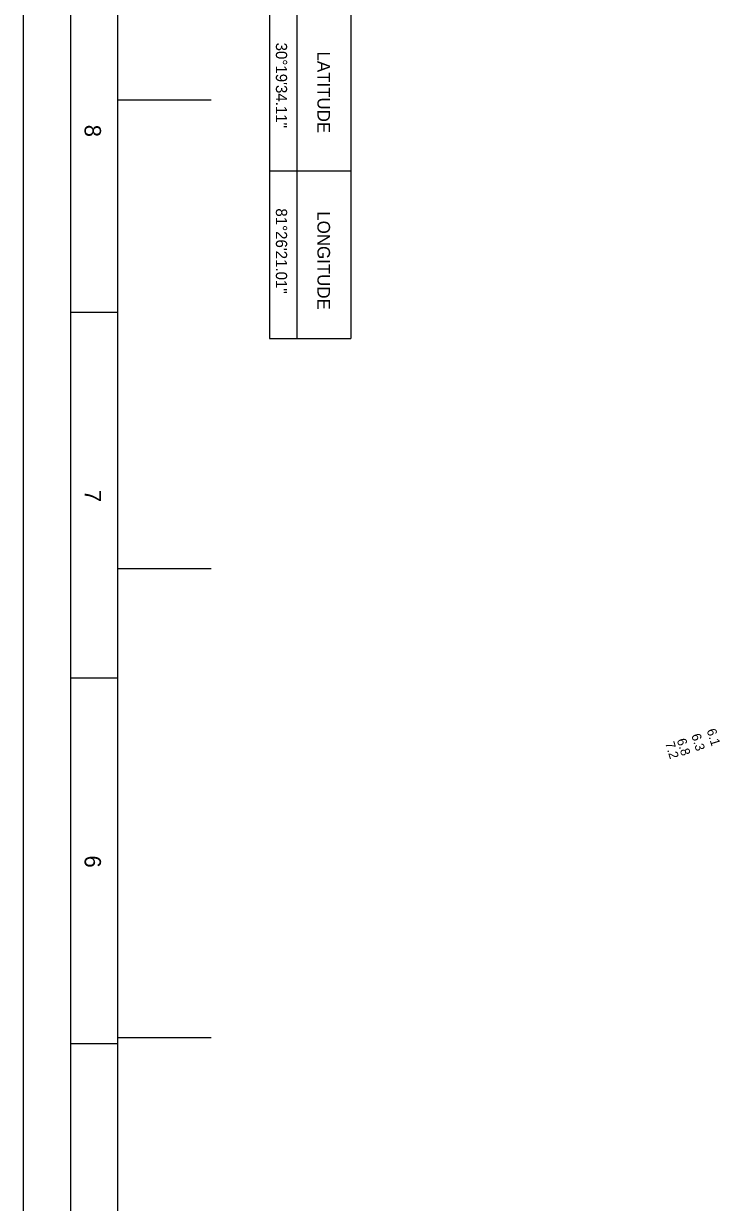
# Model space of a CAD drawing. Extents: x 516226 to 519626, y 2175719 to 2180119.
# Drawn here: x 516226 to 516969, y 2177824 to 2179082 of the extents above; entities that cross this region are included whole.
import ezdxf

# ---------------------------------------------------------------- set-up
doc = ezdxf.new("R2010")
doc.units = 0
for name, color, linetype in [('G-ANNO-NPLT', 7, 'Continuous'), ('G-ANNO-TTLB', 7, 'Continuous'), ('V-ANNO-SCHD', 7, 'Continuous'), ('V-ANNO-SYMB', 7, 'Continuous'), ('V-TOPO-COOR-STAT', 7, 'Continuous'), ('V-TOPO-SOUN', 7, 'Continuous')]:
    doc.layers.add(name, color=color, linetype=linetype)

msp = doc.modelspace()

# ---------------------------------------------------------------- linework, layer by layer
at = {"layer": 'G-ANNO-NPLT'}
msp.add_lwpolyline([(519626, 2180118.8), (519626, 2175718.8), (516226, 2175718.8), (516226, 2180118.8)], close=True, dxfattribs=at)
at = {"layer": 'G-ANNO-TTLB'}
for p, q in [((516276, 2178773.8), (516326, 2178773.8)), ((516276, 2178383.8), (516326, 2178383.8)), ((516276, 2177993.8), (516326, 2177993.8))]:
    msp.add_line(p, q, dxfattribs=at)
for points in [[(516276, 2180068.8), (516276, 2175768.8), (519576, 2175768.8), (519576, 2180068.8)], [(519526, 2175818.8), (519526, 2179943.8), (516326, 2179943.8), (516326, 2175818.8)]]:
    msp.add_lwpolyline(points, close=True, dxfattribs=at)
at = {"layer": 'V-ANNO-SCHD'}
for p, q in [((516488.2, 2179609.9), (516488.2, 2178745.9)), ((516517.1, 2179609.9), (516517.1, 2178745.9)), ((516574.8, 2179609.9), (516574.8, 2178745.9)), ((516574.8, 2178924.2), (516488.2, 2178924.2)), ((516488.2, 2178745.9), (516574.8, 2178745.9))]:
    msp.add_line(p, q, dxfattribs=at)
at = {"layer": 'V-TOPO-COOR-STAT'}
for p, q in [((516426, 2179000), (516326, 2179000)), ((516426, 2178500), (516326, 2178500)), ((516426, 2178000), (516326, 2178000))]:
    msp.add_line(p, q, dxfattribs=at)

# ---------------------------------------------------------------- texts
at = {"layer": 'G-ANNO-TTLB'}
for s, p in [('8', (516291, 2178973.8)), ('7', (516291, 2178584.4)), ('6', (516291, 2178194.4))]:
    msp.add_text(s, height=17.5, rotation=270, dxfattribs=at).set_placement(p)
at = {"layer": 'V-ANNO-SCHD'}
for s, p in [('LATITUDE', (516539.2, 2179051.9)), ('LONGITUDE', (516539.2, 2178881.5))]:
    msp.add_text(s, height=13.47, rotation=270.0001, dxfattribs=at).set_placement(p)
at = {"layer": 'V-ANNO-SYMB'}
for s, p in [('30%%D19\'34.11"', (516494.9, 2179061.4)), ('81%%D26\'21.01"', (516494.9, 2178884.6))]:
    msp.add_text(s, height=12, rotation=270, dxfattribs=at).set_placement(p)
at = {"layer": 'V-TOPO-SOUN'}
for s, p in [('6.1', (516954, 2178328)), ('6.8', (516922.1, 2178317.6)), ('6.3', (516937.6, 2178322.7)), ('7.2', (516909.7, 2178314.2))]:
    msp.add_text(s, height=10, rotation=287.212, dxfattribs=at).set_placement(p)

doc.saveas('drawing.dxf')
